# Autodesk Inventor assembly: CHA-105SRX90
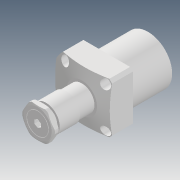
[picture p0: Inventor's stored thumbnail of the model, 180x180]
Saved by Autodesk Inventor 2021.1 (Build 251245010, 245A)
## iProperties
Created: 2019-05
Part Number: CHA-105SRX90
Description: STEP AP203
Document SubType Name: Assembly
Designer: user
Title: CHA-105SRX90.STEP
Revision Number: ÈÎºÎ
Sending System: SolidWorks 2017
Preprocessor: SwSTEP 2.0
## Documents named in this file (5)
- D:\Vault_2016\Projekty\Clamptek\Hydraulic\CHA\CHA\CHA-105\Inventor\CHA-105SRX90\CHA-105SRX90.iam
- D:\Vault_2016\Projekty\Clamptek\Hydraulic\CHA\CHA\CHA-105\Inventor\CHA-105SRX90\CHA-105BT.ipt
- D:\Vault_2016\Projekty\Clamptek\Hydraulic\CHA\CHA\CHA-105\Inventor\CHA-105SRX90\CHA-105S×¶Ì×.ipt
- D:\Vault_2016\Projekty\Clamptek\Hydraulic\CHA\CHA\CHA-105\Inventor\CHA-105SRX90\CHA-105S»îÈû¸Ë.ipt
- D:\Vault_2016\Projekty\Clamptek\Hydraulic\CHA\CHA\CHA-105\Inventor\CHA-105SRX90\CHA-105ÂÝÄ¸.ipt
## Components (4 placed, 4 different names)
1. CHA-105BT_1
2. CHA-105S×¶Ì×_2
3. CHA-105S»îÈû¸Ë_3
4. CHA-105ÂÝÄ¸_4
